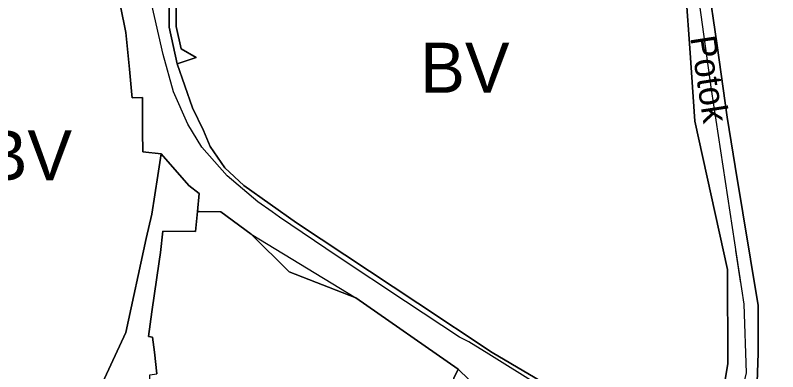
# Model space of a CAD drawing. Extents: x -555509 to -553005, y -1186756 to -1182560.
# Drawn here: x -554629.7 to -554416.4, y -1185177.8 to -1185078 of the extents above; entities that cross this region are included whole.
import ezdxf

# ---------------------------------------------------------------- set-up
doc = ezdxf.new("R2010")
doc.units = 0
for name, color, linetype in [('Level 15', 7, 'Continuous'), ('Level 31', 7, 'Continuous'), ('Level 57', 7, 'Continuous'), ('Level 59', 7, 'Continuous'), ('OBRYS_PLOCH', 7, 'Continuous'), ('stav_BV', 7, 'Continuous'), ('stav_DS', 7, 'Continuous'), ('stav_PU', 7, 'Continuous')]:
    doc.layers.add(name, color=color, linetype=linetype)

msp = doc.modelspace()

# ---------------------------------------------------------------- linework, layer by layer
at = {"layer": 'Level 15'}
for points in [[(-554580.13, -1185103.97), (-554584.39, -1185091.65), (-554586.65, -1185081.39), (-554586.78, -1185057.34)], [(-554442.61, -1185064.27), (-554440.97, -1185087.23)], [(-554433.33, -1185086.52), (-554436.06, -1185067.91)], [(-554600.21, -1185075.52), (-554598.7, -1185082.85)], [(-554598.7, -1185082.85), (-554597.74, -1185093.11), (-554597.07, -1185100.3), (-554596.99, -1185101.14), (-554594.12, -1185101.04)], [(-554440.97, -1185087.23), (-554439.52, -1185107.65), (-554430.41, -1185149.16), (-554430.3, -1185175.48)], [(-554430.56, -1185106.52), (-554433.33, -1185086.52)], [(-554594.12, -1185101.04), (-554594.07, -1185110.52)], [(-554571.01, -1185120.7), (-554575.11, -1185114.8), (-554576.99, -1185110.26), (-554580.13, -1185103.97)], [(-554428.26, -1185120.39), (-554430.56, -1185106.52)], [(-554594.07, -1185110.52), (-554594.03, -1185116.25), (-554588.84, -1185116.84)], [(-554588.84, -1185116.84), (-554589.77, -1185122.85)], [(-554578.72, -1185132.96), (-554578.27, -1185127.94), (-554581.14, -1185125.67), (-554588.84, -1185116.84)], [(-554578.72, -1185132.96), (-554578.27, -1185127.94), (-554581.14, -1185125.67), (-554588.84, -1185116.84)], [(-554588.84, -1185116.84), (-554581.14, -1185125.67), (-554578.27, -1185127.94), (-554578.72, -1185132.96)], [(-554551.01, -1185136.14), (-554565.7, -1185125.67), (-554571.01, -1185120.7)], [(-554421.81, -1185172.56), (-554421.8, -1185159.23), (-554428.26, -1185120.39)], [(-554589.77, -1185122.85), (-554591.5, -1185133.68), (-554593.05, -1185140.46), (-554598.76, -1185166.79)], [(-554591.08, -1185196.55), (-554592.18, -1185189.75), (-554592.19, -1185188.51), (-554592.21, -1185185.83), (-554591.98, -1185178.64), (-554590.1, -1185178.4), (-554590.75, -1185172.34), (-554591.27, -1185168.14), (-554592.41, -1185167.95), (-554591.42, -1185160.99), (-554589.41, -1185146.9), (-554589.05, -1185144.39), (-554588.35, -1185138.49), (-554579.27, -1185138.58), (-554578.72, -1185132.96)], [(-554578.72, -1185132.96), (-554578.19, -1185132.96), (-554572.16, -1185133.07), (-554563.71, -1185139.26), (-554553.08, -1185149.81)], [(-554461.76, -1185192.75), (-554479.03, -1185182.53), (-554496.22, -1185172.35), (-554517.07, -1185158.57), (-554551.01, -1185136.14)], [(-554553.08, -1185149.81), (-554534.36, -1185157.1), (-554534.36, -1185157.1)], [(-554534.36, -1185157.1), (-554505.75, -1185177.03)], [(-554598.76, -1185166.79), (-554607.1, -1185184.92), (-554613.87, -1185198.73), (-554631.94, -1185230), (-554645.24, -1185255.79), (-554660.25, -1185284.19), (-554660.25, -1185284.19)], [(-554428.5, -1185209.75), (-554425.44, -1185199.67), (-554422.14, -1185180.67), (-554421.81, -1185172.56)], [(-554505.75, -1185177.03), (-554506.95, -1185179.58), (-554511.53, -1185190.38), (-554513.23, -1185196.57), (-554511.57, -1185206.96), (-554509.28, -1185221.24)], [(-554430.3, -1185175.48), (-554434.27, -1185199.46)]]:
    msp.add_lwpolyline(points, dxfattribs=at)
msp.add_lwpolyline([(-554584.39, -1185091.65), (-554579.05, -1185089.9), (-554583.27, -1185087.43), (-554584.65, -1185081.16), (-554584.74, -1185064.37), (-554582.65, -1185058.6), (-554582.39, -1185057.83), (-554586.78, -1185057.34), (-554586.65, -1185081.39)], close=True, dxfattribs=at)
at = {"layer": 'Level 31'}
for points in [[(-553997.29, -1184320.09), (-554016.36, -1184366.23), (-554036.46, -1184409.26), (-554049.09, -1184432.2), (-554098.06, -1184473.18), (-554142.9, -1184516.99), (-554206.3, -1184543.54), (-554246.24, -1184609), (-554366.6, -1184711.57), (-554375.17, -1184735.92), (-554380.97, -1184742.11), (-554402.36, -1184756.03), (-554415.63, -1184766.72), (-554409.45, -1184838.88), (-554423.36, -1184867.62), (-554433.16, -1184895.06), (-554448.23, -1184939.39), (-554444.24, -1184998.93), (-554443.72, -1185035.39), (-554434.96, -1185098.79), (-554425.81, -1185158.84), (-554425.17, -1185178.04), (-554431.86, -1185204.97), (-554445.49, -1185223.21)], [(-554426.7, -1185152.98), (-554428.09, -1185143.88)]]:
    msp.add_lwpolyline(points, dxfattribs=at)
at = {"layer": 'OBRYS_PLOCH'}
for p, q in [((-554440.97, -1185087.23), (-554442.61, -1185064.27)), ((-554440.97, -1185087.23), (-554442.61, -1185064.27)), ((-554588.32, -1185089.02), (-554592.54, -1185070.28)), ((-554600.21, -1185075.52), (-554598.7, -1185082.85)), ((-554585.41, -1185099.46), (-554588.32, -1185089.02)), ((-554584.39, -1185091.65), (-554580.13, -1185103.97)), ((-554584.39, -1185091.65), (-554580.13, -1185103.97)), ((-554597.07, -1185100.3), (-554596.99, -1185101.14)), ((-554581.42, -1185108.47), (-554585.41, -1185099.46)), ((-554596.99, -1185101.14), (-554594.12, -1185101.04)), ((-554594.12, -1185101.04), (-554594.07, -1185110.52)), ((-554577.44, -1185114.97), (-554581.42, -1185108.47)), ((-554570.4, -1185122.97), (-554577.44, -1185114.97)), ((-554588.84, -1185116.84), (-554581.14, -1185125.67)), ((-554561.81, -1185130.28), (-554570.4, -1185122.97)), ((-554581.14, -1185125.67), (-554578.27, -1185127.94)), ((-554578.27, -1185127.94), (-554578.72, -1185132.96)), ((-554557.82, -1185133.08), (-554561.81, -1185130.28)), ((-554578.72, -1185132.96), (-554578.19, -1185132.96)), ((-554578.19, -1185132.96), (-554572.16, -1185133.07)), ((-554572.16, -1185133.07), (-554563.71, -1185139.26)), ((-554563.71, -1185139.26), (-554534.36, -1185157.1)), ((-554520.51, -1185158.16), (-554539.63, -1185145.46)), ((-554534.36, -1185157.1), (-554505.75, -1185177.03)), ((-554505.44, -1185168.07), (-554520.51, -1185158.16)), ((-554502.77, -1185169.44), (-554505.44, -1185168.07)), ((-554497.22, -1185172.86), (-554502.77, -1185169.44)), ((-554483.26, -1185181.57), (-554497.22, -1185172.86)), ((-554505.75, -1185177.03), (-554499.53, -1185183.06)), ((-554434.27, -1185199.46), (-554430.3, -1185175.48)), ((-554434.27, -1185199.46), (-554430.3, -1185175.48))]:
    msp.add_line(p, q, dxfattribs=at)
for points in [[(-554411.42, -1184861.42), (-554417.73, -1184866.61), (-554423.44, -1184878.9), (-554428.93, -1184893.38), (-554433.55, -1184907.81), (-554438.97, -1184924.63), (-554444.48, -1184941.75), (-554441.89, -1184961.68), (-554441.47, -1184975.55), (-554440.57, -1185000.53), (-554439.7, -1185020.93), (-554440.32, -1185034.58), (-554438.35, -1185050), (-554436.06, -1185067.91), (-554433.33, -1185086.52), (-554430.56, -1185106.52), (-554428.26, -1185120.39)], [(-554598.76, -1185166.79), (-554593.05, -1185140.46), (-554591.5, -1185133.68), (-554589.77, -1185122.85), (-554588.84, -1185116.84), (-554594.03, -1185116.25), (-554594.07, -1185110.52), (-554594.12, -1185101.04), (-554596.99, -1185101.14), (-554597.07, -1185100.3), (-554597.74, -1185093.11), (-554598.7, -1185082.85), (-554600.21, -1185075.52), (-554604.52, -1185060.98), (-554605.27, -1185061.33), (-554618.43, -1185046.91), (-554618.17, -1185046.53), (-554633.81, -1185033.88), (-554651.99, -1185023.61), (-554658.03, -1185036.7), (-554661.01, -1185042.53), (-554663.23, -1185046.19), (-554664.37, -1185049.89), (-554666.18, -1185059.07)], [(-554586.78, -1185057.34), (-554582.39, -1185057.83), (-554582.65, -1185058.6), (-554584.74, -1185064.37), (-554584.65, -1185081.16), (-554583.27, -1185087.43)], [(-554586.78, -1185057.34), (-554582.39, -1185057.83), (-554582.65, -1185058.6), (-554584.74, -1185064.37), (-554584.65, -1185081.16), (-554583.27, -1185087.43)], [(-554598.7, -1185082.85), (-554597.74, -1185093.11), (-554597.07, -1185100.3)], [(-554583.27, -1185087.43), (-554579.05, -1185089.9), (-554584.39, -1185091.65)], [(-554583.27, -1185087.43), (-554579.05, -1185089.9), (-554584.39, -1185091.65)], [(-554430.3, -1185175.48), (-554430.41, -1185149.16), (-554439.52, -1185107.65), (-554440.97, -1185087.23)], [(-554430.3, -1185175.48), (-554430.41, -1185149.16), (-554439.52, -1185107.65), (-554440.97, -1185087.23)], [(-554580.13, -1185103.97), (-554576.99, -1185110.26), (-554575.11, -1185114.8), (-554571.01, -1185120.7)], [(-554580.13, -1185103.97), (-554576.99, -1185110.26), (-554575.11, -1185114.8), (-554571.01, -1185120.7)], [(-554594.07, -1185110.52), (-554594.03, -1185116.25), (-554588.84, -1185116.84)], [(-554578.72, -1185132.96), (-554578.27, -1185127.94), (-554581.14, -1185125.67), (-554588.84, -1185116.84)], [(-554571.01, -1185120.7), (-554565.7, -1185125.67), (-554551.01, -1185136.14)], [(-554571.01, -1185120.7), (-554565.7, -1185125.67), (-554551.01, -1185136.14)], [(-554428.26, -1185120.39), (-554421.8, -1185159.23), (-554421.81, -1185172.56), (-554422.14, -1185180.67), (-554425.44, -1185199.67), (-554428.5, -1185209.75)], [(-554506.95, -1185179.58), (-554505.75, -1185177.03), (-554534.36, -1185157.1), (-554553.08, -1185149.81), (-554563.71, -1185139.26), (-554572.16, -1185133.07), (-554578.19, -1185132.96), (-554578.72, -1185132.96), (-554579.27, -1185138.58), (-554588.35, -1185138.49), (-554589.05, -1185144.39), (-554589.41, -1185146.9), (-554591.42, -1185160.99), (-554592.41, -1185167.95), (-554591.27, -1185168.14), (-554590.75, -1185172.34), (-554590.1, -1185178.4)], [(-554539.63, -1185145.46), (-554555.72, -1185134.51), (-554557.82, -1185133.08)], [(-554551.01, -1185136.14), (-554517.07, -1185158.57), (-554496.22, -1185172.35), (-554479.03, -1185182.53), (-554461.76, -1185192.75)], [(-554551.01, -1185136.14), (-554517.07, -1185158.57), (-554496.22, -1185172.35), (-554479.03, -1185182.53), (-554461.76, -1185192.75)], [(-554660.25, -1185284.19), (-554645.24, -1185255.79), (-554631.94, -1185230), (-554613.87, -1185198.73), (-554607.1, -1185184.92), (-554598.76, -1185166.79)]]:
    msp.add_lwpolyline(points, dxfattribs=at)
at = {"layer": 'stav_BV'}
for p, q in [((-554440.97, -1185087.23), (-554442.61, -1185064.27)), ((-554584.39, -1185091.65), (-554580.13, -1185103.97)), ((-554434.27, -1185199.46), (-554430.3, -1185175.48))]:
    msp.add_line(p, q, dxfattribs=at)
for points in [[(-554411.42, -1184861.42), (-554417.73, -1184866.61), (-554423.44, -1184878.9), (-554428.93, -1184893.38), (-554433.55, -1184907.81), (-554438.97, -1184924.63), (-554444.48, -1184941.75), (-554441.89, -1184961.68), (-554441.47, -1184975.55), (-554440.57, -1185000.53), (-554439.7, -1185020.93), (-554440.32, -1185034.58), (-554438.35, -1185050), (-554436.06, -1185067.91), (-554433.33, -1185086.52), (-554430.56, -1185106.52), (-554428.26, -1185120.39)], [(-554598.76, -1185166.79), (-554593.05, -1185140.46), (-554591.5, -1185133.68), (-554589.77, -1185122.85), (-554588.84, -1185116.84), (-554594.03, -1185116.25), (-554594.07, -1185110.52), (-554594.12, -1185101.04), (-554596.99, -1185101.14), (-554597.07, -1185100.3), (-554597.74, -1185093.11), (-554598.7, -1185082.85), (-554600.21, -1185075.52), (-554604.52, -1185060.98), (-554605.27, -1185061.33), (-554618.43, -1185046.91), (-554618.17, -1185046.53), (-554633.81, -1185033.88), (-554651.99, -1185023.61), (-554658.03, -1185036.7), (-554661.01, -1185042.53), (-554663.23, -1185046.19), (-554664.37, -1185049.89), (-554666.18, -1185059.07)], [(-554586.78, -1185057.34), (-554582.39, -1185057.83), (-554582.65, -1185058.6), (-554584.74, -1185064.37), (-554584.65, -1185081.16), (-554583.27, -1185087.43)], [(-554583.27, -1185087.43), (-554579.05, -1185089.9), (-554584.39, -1185091.65)], [(-554430.3, -1185175.48), (-554430.41, -1185149.16), (-554439.52, -1185107.65), (-554440.97, -1185087.23)], [(-554580.13, -1185103.97), (-554576.99, -1185110.26), (-554575.11, -1185114.8), (-554571.01, -1185120.7)], [(-554571.01, -1185120.7), (-554565.7, -1185125.67), (-554551.01, -1185136.14)], [(-554428.26, -1185120.39), (-554421.8, -1185159.23), (-554421.81, -1185172.56), (-554422.14, -1185180.67), (-554425.44, -1185199.67), (-554428.5, -1185209.75)], [(-554506.95, -1185179.58), (-554505.75, -1185177.03), (-554534.36, -1185157.1), (-554553.08, -1185149.81), (-554563.71, -1185139.26), (-554572.16, -1185133.07), (-554578.19, -1185132.96), (-554578.72, -1185132.96), (-554579.27, -1185138.58), (-554588.35, -1185138.49), (-554589.05, -1185144.39), (-554589.41, -1185146.9), (-554591.42, -1185160.99), (-554592.41, -1185167.95), (-554591.27, -1185168.14), (-554590.75, -1185172.34), (-554590.1, -1185178.4)], [(-554551.01, -1185136.14), (-554517.07, -1185158.57), (-554496.22, -1185172.35), (-554479.03, -1185182.53), (-554461.76, -1185192.75)], [(-554660.25, -1185284.19), (-554645.24, -1185255.79), (-554631.94, -1185230), (-554613.87, -1185198.73), (-554607.1, -1185184.92), (-554598.76, -1185166.79)]]:
    msp.add_lwpolyline(points, dxfattribs=at)
at = {"layer": 'stav_DS'}
for p, q in [((-554588.32, -1185089.02), (-554592.54, -1185070.28)), ((-554600.21, -1185075.52), (-554598.7, -1185082.85)), ((-554598.7, -1185082.85), (-554597.74, -1185093.11)), ((-554585.41, -1185099.46), (-554588.32, -1185089.02)), ((-554597.74, -1185093.11), (-554597.07, -1185100.3)), ((-554597.07, -1185100.3), (-554596.99, -1185101.14)), ((-554581.42, -1185108.47), (-554585.41, -1185099.46)), ((-554596.99, -1185101.14), (-554594.12, -1185101.04)), ((-554594.12, -1185101.04), (-554594.07, -1185110.52)), ((-554577.44, -1185114.97), (-554581.42, -1185108.47)), ((-554594.07, -1185110.52), (-554594.03, -1185116.25)), ((-554570.4, -1185122.97), (-554577.44, -1185114.97)), ((-554594.03, -1185116.25), (-554588.84, -1185116.84)), ((-554588.84, -1185116.84), (-554581.14, -1185125.67)), ((-554561.81, -1185130.28), (-554570.4, -1185122.97)), ((-554581.14, -1185125.67), (-554578.27, -1185127.94)), ((-554578.27, -1185127.94), (-554578.72, -1185132.96)), ((-554557.82, -1185133.08), (-554561.81, -1185130.28)), ((-554578.72, -1185132.96), (-554578.19, -1185132.96)), ((-554563.71, -1185139.26), (-554534.36, -1185157.1)), ((-554520.51, -1185158.16), (-554539.63, -1185145.46)), ((-554534.36, -1185157.1), (-554505.75, -1185177.03)), ((-554505.44, -1185168.07), (-554520.51, -1185158.16)), ((-554502.77, -1185169.44), (-554505.44, -1185168.07)), ((-554497.22, -1185172.86), (-554502.77, -1185169.44)), ((-554483.26, -1185181.57), (-554497.22, -1185172.86)), ((-554505.75, -1185177.03), (-554499.53, -1185183.06))]:
    msp.add_line(p, q, dxfattribs=at)
for points in [[(-554578.19, -1185132.96), (-554572.16, -1185133.07), (-554563.71, -1185139.26)], [(-554539.63, -1185145.46), (-554555.72, -1185134.51), (-554557.82, -1185133.08)]]:
    msp.add_lwpolyline(points, dxfattribs=at)
at = {"layer": 'stav_PU'}
for p, q in [((-554442.61, -1185064.27), (-554440.97, -1185087.23)), ((-554433.33, -1185086.52), (-554436.06, -1185067.91)), ((-554600.21, -1185075.52), (-554598.7, -1185082.85)), ((-554430.56, -1185106.52), (-554433.33, -1185086.52)), ((-554580.13, -1185103.97), (-554584.39, -1185091.65)), ((-554594.12, -1185101.04), (-554594.07, -1185110.52)), ((-554428.26, -1185120.39), (-554430.56, -1185106.52)), ((-554588.84, -1185116.84), (-554589.77, -1185122.85)), ((-554553.08, -1185149.81), (-554534.36, -1185157.1)), ((-554534.36, -1185157.1), (-554505.75, -1185177.03)), ((-554430.3, -1185175.48), (-554434.27, -1185199.46))]:
    msp.add_line(p, q, dxfattribs=at)
for points in [[(-554584.39, -1185091.65), (-554579.05, -1185089.9), (-554583.27, -1185087.43), (-554584.65, -1185081.16), (-554584.74, -1185064.37), (-554582.65, -1185058.6), (-554582.39, -1185057.83), (-554586.78, -1185057.34)], [(-554598.7, -1185082.85), (-554597.74, -1185093.11), (-554597.07, -1185100.3), (-554596.99, -1185101.14), (-554594.12, -1185101.04)], [(-554440.97, -1185087.23), (-554439.52, -1185107.65), (-554430.41, -1185149.16), (-554430.3, -1185175.48)], [(-554571.01, -1185120.7), (-554575.11, -1185114.8), (-554576.99, -1185110.26), (-554580.13, -1185103.97)], [(-554594.07, -1185110.52), (-554594.03, -1185116.25), (-554588.84, -1185116.84)], [(-554578.72, -1185132.96), (-554578.27, -1185127.94), (-554581.14, -1185125.67), (-554588.84, -1185116.84)], [(-554551.01, -1185136.14), (-554565.7, -1185125.67), (-554571.01, -1185120.7)], [(-554421.81, -1185172.56), (-554421.8, -1185159.23), (-554428.26, -1185120.39)], [(-554589.77, -1185122.85), (-554591.5, -1185133.68), (-554593.05, -1185140.46), (-554598.76, -1185166.79)], [(-554591.08, -1185196.55), (-554592.18, -1185189.75), (-554592.19, -1185188.51), (-554592.21, -1185185.83), (-554591.98, -1185178.64), (-554590.1, -1185178.4), (-554590.75, -1185172.34), (-554591.27, -1185168.14), (-554592.41, -1185167.95), (-554591.42, -1185160.99), (-554589.41, -1185146.9), (-554589.05, -1185144.39), (-554588.35, -1185138.49), (-554579.27, -1185138.58), (-554578.72, -1185132.96)], [(-554578.72, -1185132.96), (-554578.19, -1185132.96), (-554572.16, -1185133.07), (-554563.71, -1185139.26), (-554553.08, -1185149.81)], [(-554461.76, -1185192.75), (-554479.03, -1185182.53), (-554496.22, -1185172.35), (-554517.07, -1185158.57), (-554551.01, -1185136.14)], [(-554598.76, -1185166.79), (-554607.1, -1185184.92), (-554613.87, -1185198.73), (-554631.94, -1185230), (-554645.24, -1185255.79), (-554660.25, -1185284.19)], [(-554428.5, -1185209.75), (-554425.44, -1185199.67), (-554422.14, -1185180.67), (-554421.81, -1185172.56)], [(-554505.75, -1185177.03), (-554506.95, -1185179.58), (-554511.53, -1185190.38), (-554513.23, -1185196.57), (-554511.57, -1185206.96), (-554509.28, -1185221.24)]]:
    msp.add_lwpolyline(points, dxfattribs=at)

# ---------------------------------------------------------------- texts
at = {"layer": 'Level 57'}
msp.add_text('Potok', height=7.174, rotation=278.7148, dxfattribs=at).set_placement((-554440.87, -1185084.27))
at = {"layer": 'Level 59'}
for p in [(-554516.37, -1185099.72), (-554638.76, -1185124.24)]:
    msp.add_text('BV', height=14, dxfattribs=at).set_placement(p)

doc.saveas('drawing.dxf')
